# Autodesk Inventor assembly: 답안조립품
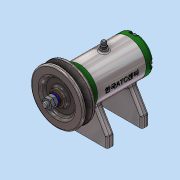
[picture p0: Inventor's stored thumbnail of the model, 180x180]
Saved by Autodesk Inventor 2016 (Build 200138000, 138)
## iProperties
Created: 2018-05
Part Number: 답안조립품
Document SubType Name: Assembly
Designer: 301-08
Author: 301-08
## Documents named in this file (15)
- C:\Users\301-08\Desktop\480507V1020\답안조립품.iam
- C:\Users\301-08\Desktop\480507V1020\본체.ipt
- C:\Users\301-08\Desktop\480507V1020\축.ipt
- C:\Users\301-08\Desktop\480507V1020\베어링 6002.ipt
- C:\Users\301-08\Desktop\480507V1020\뒤커버.ipt
- C:\Users\301-08\Desktop\480507V1020\볼트 M4x12.ipt
- C:\Users\301-08\Desktop\480507V1020\앞커버.ipt
- C:\Users\301-08\Desktop\480507V1020\키 3x3x12.ipt
- C:\Users\301-08\Desktop\480507V1020\V벨트풀리.ipt
- C:\Users\301-08\Desktop\480507V1020\와셔 8x17.ipt
- C:\Users\301-08\Desktop\480507V1020\스프링와셔 8.ipt
- C:\Users\301-08\Desktop\480507V1020\너트 M8.ipt
- C:\Users\301-08\Desktop\480507V1020\니플 M6x0.75.ipt
- C:\Users\301-08\Desktop\480507V1020\와셔 6x11.5.ipt
- C:\Users\301-08\Desktop\480507V1020\볼트 M6x8.ipt
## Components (1 placed, 1 different names)
1. V벨트풀리:1
